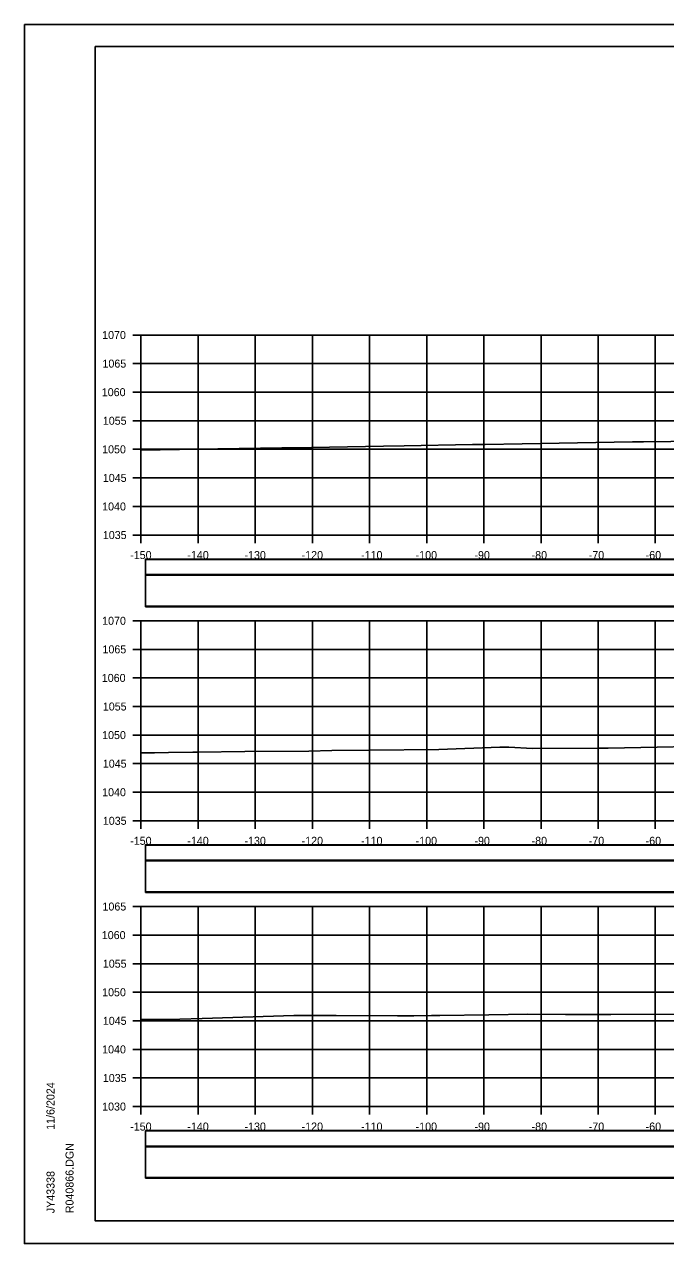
# Model space of a CAD drawing. Extents: x 1370565 to 1374448, y 301010 to 304637.
# Drawn here: x 1373198.4 to 1373310.6, y 303218.4 to 303431.7 of the extents above; entities that cross this region are included whole.
import ezdxf

# ---------------------------------------------------------------- set-up
doc = ezdxf.new("R2010")
doc.units = 0
for name, color, linetype in [('Default', 7, 'Continuous'), ('R_Axis', 7, 'Continuous'), ('R_Axis Annot', 7, 'Continuous'), ('R_Border', 7, 'Continuous'), ('R_Drive', 7, 'Continuous'), ('R_Exist Surface', 7, 'Continuous'), ('R_Grid', 7, 'Continuous'), ('R_No Plot', 7, 'Continuous')]:
    doc.layers.add(name, color=color, linetype=linetype)

msp = doc.modelspace()

# ---------------------------------------------------------------- linework, layer by layer
at = {"layer": 'Default'}
for points in [[(1373219.61, 303335.38), (1373518.02, 303335.38), (1373518.02, 303338.08), (1373219.61, 303338.08)], [(1373219.61, 303329.8), (1373518.02, 303329.8), (1373518.02, 303335.32), (1373219.61, 303335.32)], [(1373219.61, 303285.38), (1373518.02, 303285.38), (1373518.02, 303288.08), (1373219.61, 303288.08)], [(1373219.61, 303279.8), (1373518.02, 303279.8), (1373518.02, 303285.32), (1373219.61, 303285.32)], [(1373219.61, 303235.38), (1373518.02, 303235.38), (1373518.02, 303238.08), (1373219.61, 303238.08)], [(1373219.61, 303229.8), (1373518.02, 303229.8), (1373518.02, 303235.32), (1373219.61, 303235.32)]]:
    msp.add_lwpolyline(points, close=True, dxfattribs=at)
at = {"layer": 'R_Axis'}
for p, q in [((1373217.41, 303377.34), (1373218.81, 303377.34)), ((1373218.81, 303342.34), (1373218.81, 303377.34)), ((1373217.41, 303372.34), (1373218.81, 303372.34)), ((1373217.41, 303367.34), (1373218.81, 303367.34)), ((1373217.41, 303362.34), (1373218.81, 303362.34)), ((1373217.41, 303357.34), (1373218.81, 303357.34)), ((1373217.41, 303352.34), (1373218.81, 303352.34)), ((1373217.41, 303347.34), (1373218.81, 303347.34)), ((1373217.41, 303342.34), (1373218.81, 303342.34)), ((1373218.81, 303342.34), (1373518.81, 303342.34)), ((1373218.81, 303340.94), (1373218.81, 303342.34)), ((1373228.81, 303340.94), (1373228.81, 303342.34)), ((1373238.81, 303340.94), (1373238.81, 303342.34)), ((1373248.81, 303340.94), (1373248.81, 303342.34)), ((1373258.81, 303340.94), (1373258.81, 303342.34)), ((1373268.81, 303340.94), (1373268.81, 303342.34)), ((1373278.81, 303340.94), (1373278.81, 303342.34)), ((1373288.81, 303340.94), (1373288.81, 303342.34)), ((1373298.81, 303340.94), (1373298.81, 303342.34)), ((1373308.81, 303340.94), (1373308.81, 303342.34)), ((1373217.41, 303327.34), (1373218.81, 303327.34)), ((1373218.81, 303292.34), (1373218.81, 303327.34)), ((1373217.41, 303322.34), (1373218.81, 303322.34)), ((1373217.41, 303317.34), (1373218.81, 303317.34)), ((1373217.41, 303312.34), (1373218.81, 303312.34)), ((1373217.41, 303307.34), (1373218.81, 303307.34)), ((1373217.41, 303302.34), (1373218.81, 303302.34)), ((1373217.41, 303297.34), (1373218.81, 303297.34)), ((1373217.41, 303292.34), (1373218.81, 303292.34)), ((1373218.81, 303292.34), (1373518.81, 303292.34)), ((1373218.81, 303290.94), (1373218.81, 303292.34)), ((1373228.81, 303290.94), (1373228.81, 303292.34)), ((1373238.81, 303290.94), (1373238.81, 303292.34)), ((1373248.81, 303290.94), (1373248.81, 303292.34)), ((1373258.81, 303290.94), (1373258.81, 303292.34)), ((1373268.81, 303290.94), (1373268.81, 303292.34)), ((1373278.81, 303290.94), (1373278.81, 303292.34)), ((1373288.81, 303290.94), (1373288.81, 303292.34)), ((1373298.81, 303290.94), (1373298.81, 303292.34)), ((1373308.81, 303290.94), (1373308.81, 303292.34)), ((1373217.41, 303277.34), (1373218.81, 303277.34)), ((1373218.81, 303242.34), (1373218.81, 303277.34)), ((1373217.41, 303272.34), (1373218.81, 303272.34)), ((1373217.41, 303267.34), (1373218.81, 303267.34)), ((1373217.41, 303262.34), (1373218.81, 303262.34)), ((1373217.41, 303257.34), (1373218.81, 303257.34)), ((1373217.41, 303252.34), (1373218.81, 303252.34)), ((1373217.41, 303247.34), (1373218.81, 303247.34)), ((1373217.41, 303242.34), (1373218.81, 303242.34)), ((1373218.81, 303242.34), (1373518.81, 303242.34)), ((1373218.81, 303240.94), (1373218.81, 303242.34)), ((1373228.81, 303240.94), (1373228.81, 303242.34)), ((1373238.81, 303240.94), (1373238.81, 303242.34)), ((1373248.81, 303240.94), (1373248.81, 303242.34)), ((1373258.81, 303240.94), (1373258.81, 303242.34)), ((1373268.81, 303240.94), (1373268.81, 303242.34)), ((1373278.81, 303240.94), (1373278.81, 303242.34)), ((1373288.81, 303240.94), (1373288.81, 303242.34)), ((1373298.81, 303240.94), (1373298.81, 303242.34)), ((1373308.81, 303240.94), (1373308.81, 303242.34))]:
    msp.add_line(p, q, dxfattribs=at)
at = {"layer": 'R_Border'}
for p, q in [((1373210.81, 303427.8), (1373526.99, 303427.8)), ((1373210.81, 303222.34), (1373210.81, 303427.8)), ((1373210.81, 303222.34), (1373210.81, 303222.34)), ((1373526.99, 303222.34), (1373210.81, 303222.34))]:
    msp.add_line(p, q, dxfattribs=at)
at = {"layer": 'R_Drive'}
for points in [[(1373219.61, 303335.43), (1373518.02, 303335.43), (1373518.02, 303338.14), (1373219.61, 303338.14)], [(1373219.61, 303329.91), (1373518.02, 303329.91), (1373518.02, 303335.43), (1373219.61, 303335.43)], [(1373219.61, 303285.43), (1373518.02, 303285.43), (1373518.02, 303288.14), (1373219.61, 303288.14)], [(1373219.61, 303279.91), (1373518.02, 303279.91), (1373518.02, 303285.43), (1373219.61, 303285.43)], [(1373219.61, 303235.43), (1373518.02, 303235.43), (1373518.02, 303238.14), (1373219.61, 303238.14)], [(1373219.61, 303229.91), (1373518.02, 303229.91), (1373518.02, 303235.43), (1373219.61, 303235.43)]]:
    msp.add_lwpolyline(points, close=True, dxfattribs=at)
at = {"layer": 'R_Exist Surface'}
for points in [[(1373218.81, 303357.17), (1373225.54, 303357.29), (1373232.27, 303357.4), (1373243.47, 303357.59), (1373248.62, 303357.68), (1373261.25, 303357.9), (1373264.87, 303357.96), (1373276.84, 303358.16), (1373279.05, 303358.19), (1373291.96, 303358.42), (1373304.8, 303358.64), (1373306.62, 303358.66), (1373306.77, 303358.66), (1373321.12, 303358.85)], [(1373218.81, 303304.23), (1373221.2, 303304.26), (1373223.61, 303304.28), (1373227.88, 303304.35), (1373228.76, 303304.37), (1373236.98, 303304.45), (1373248.16, 303304.55), (1373252.19, 303304.63), (1373258.71, 303304.69), (1373270.92, 303304.8), (1373281.61, 303305.23), (1373283.17, 303305.23), (1373287.3, 303304.97), (1373298.95, 303305.07), (1373300.17, 303305.07), (1373300.56, 303305.06), (1373323.35, 303305.53)], [(1373218.81, 303257.57), (1373222.11, 303257.57), (1373223.48, 303257.59), (1373225.62, 303257.65), (1373229.53, 303257.74), (1373245.53, 303258.3), (1373252.98, 303258.28), (1373263.7, 303258.23), (1373266.58, 303258.23), (1373269.67, 303258.3), (1373271.1, 303258.29), (1373279.69, 303258.41), (1373286.49, 303258.52), (1373293.12, 303258.43), (1373301.02, 303258.44), (1373320.91, 303258.53)]]:
    msp.add_lwpolyline(points, dxfattribs=at)
at = {"layer": 'R_Grid'}
for p, q in [((1373218.81, 303377.34), (1373518.81, 303377.34)), ((1373218.81, 303342.34), (1373218.81, 303377.34)), ((1373228.81, 303342.34), (1373228.81, 303377.34)), ((1373238.81, 303342.34), (1373238.81, 303377.34)), ((1373248.81, 303342.34), (1373248.81, 303377.34)), ((1373258.81, 303342.34), (1373258.81, 303377.34)), ((1373268.81, 303342.34), (1373268.81, 303377.34)), ((1373278.81, 303342.34), (1373278.81, 303377.34)), ((1373288.81, 303342.34), (1373288.81, 303377.34)), ((1373298.81, 303342.34), (1373298.81, 303377.34)), ((1373308.81, 303342.34), (1373308.81, 303377.34)), ((1373218.81, 303372.34), (1373518.81, 303372.34)), ((1373218.81, 303367.34), (1373518.81, 303367.34)), ((1373218.81, 303362.34), (1373518.81, 303362.34)), ((1373218.81, 303357.34), (1373518.81, 303357.34)), ((1373218.81, 303352.34), (1373518.81, 303352.34)), ((1373218.81, 303347.34), (1373518.81, 303347.34)), ((1373218.81, 303342.34), (1373518.81, 303342.34)), ((1373218.81, 303327.34), (1373518.81, 303327.34)), ((1373218.81, 303292.34), (1373218.81, 303327.34)), ((1373228.81, 303292.34), (1373228.81, 303327.34)), ((1373238.81, 303292.34), (1373238.81, 303327.34)), ((1373248.81, 303292.34), (1373248.81, 303327.34)), ((1373258.81, 303292.34), (1373258.81, 303327.34)), ((1373268.81, 303292.34), (1373268.81, 303327.34)), ((1373278.81, 303292.34), (1373278.81, 303327.34)), ((1373288.81, 303292.34), (1373288.81, 303327.34)), ((1373298.81, 303292.34), (1373298.81, 303327.34)), ((1373308.81, 303292.34), (1373308.81, 303327.34)), ((1373218.81, 303322.34), (1373518.81, 303322.34)), ((1373218.81, 303317.34), (1373518.81, 303317.34)), ((1373218.81, 303312.34), (1373518.81, 303312.34)), ((1373218.81, 303307.34), (1373518.81, 303307.34)), ((1373218.81, 303302.34), (1373518.81, 303302.34)), ((1373218.81, 303297.34), (1373518.81, 303297.34)), ((1373218.81, 303292.34), (1373518.81, 303292.34)), ((1373218.81, 303277.34), (1373518.81, 303277.34)), ((1373218.81, 303242.34), (1373218.81, 303277.34)), ((1373228.81, 303242.34), (1373228.81, 303277.34)), ((1373238.81, 303242.34), (1373238.81, 303277.34)), ((1373248.81, 303242.34), (1373248.81, 303277.34)), ((1373258.81, 303242.34), (1373258.81, 303277.34)), ((1373268.81, 303242.34), (1373268.81, 303277.34)), ((1373278.81, 303242.34), (1373278.81, 303277.34)), ((1373288.81, 303242.34), (1373288.81, 303277.34)), ((1373298.81, 303242.34), (1373298.81, 303277.34)), ((1373308.81, 303242.34), (1373308.81, 303277.34)), ((1373218.81, 303272.34), (1373518.81, 303272.34)), ((1373218.81, 303267.34), (1373518.81, 303267.34)), ((1373218.81, 303262.34), (1373518.81, 303262.34)), ((1373218.81, 303257.34), (1373518.81, 303257.34)), ((1373218.81, 303252.34), (1373518.81, 303252.34)), ((1373218.81, 303247.34), (1373518.81, 303247.34)), ((1373218.81, 303242.34), (1373518.81, 303242.34))]:
    msp.add_line(p, q, dxfattribs=at)
at = {"layer": 'R_No Plot'}
for p, q in [((1373198.41, 303431.69), (1373531.75, 303431.69)), ((1373198.41, 303218.36), (1373531.75, 303218.36))]:
    msp.add_line(p, q, dxfattribs=at)
for points in [[(1373198.41, 303431.69), (1373531.75, 303431.69), (1373531.75, 303218.36), (1373198.41, 303218.36)], [(1373444.73, 303427.8), (1373464.35, 303427.8), (1373464.35, 303417.92), (1373480.47, 303417.92), (1373503.67, 303417.92), (1373503.67, 303393.59), (1373526.99, 303393.59), (1373526.99, 303222.34), (1373210.81, 303222.34), (1373210.81, 303427.8)]]:
    msp.add_lwpolyline(points, close=True, dxfattribs=at)

# ---------------------------------------------------------------- texts
at = {"layer": 'R_Axis Annot'}
for s, p in [('1070', (1373212.01, 303376.64)), ('1065', (1373212.07, 303371.64)), ('1060', (1373211.95, 303366.64)), ('1055', (1373212.13, 303361.64)), ('1050', (1373212.01, 303356.64)), ('1045', (1373212.13, 303351.64)), ('1040', (1373212.01, 303346.64)), ('1035', (1373212.13, 303341.64)), ('-150', (1373216.92, 303338.14)), ('-140', (1373226.92, 303338.14)), ('-130', (1373236.92, 303338.14)), ('-120', (1373246.92, 303338.14)), ('-110', (1373257.32, 303338.14)), ('-100', (1373266.87, 303338.14)), ('-90', (1373277.16, 303338.14)), ('-80', (1373287.16, 303338.14)), ('-70', (1373297.16, 303338.14)), ('-60', (1373307.12, 303338.14)), ('1070', (1373212.01, 303326.64)), ('1065', (1373212.07, 303321.64)), ('1060', (1373211.95, 303316.64)), ('1055', (1373212.13, 303311.64)), ('1050', (1373212.01, 303306.64)), ('1045', (1373212.13, 303301.64)), ('1040', (1373212.01, 303296.64)), ('1035', (1373212.13, 303291.64)), ('-150', (1373216.92, 303288.14)), ('-140', (1373226.92, 303288.14)), ('-130', (1373236.92, 303288.14)), ('-120', (1373246.92, 303288.14)), ('-110', (1373257.32, 303288.14)), ('-100', (1373266.87, 303288.14)), ('-90', (1373277.16, 303288.14)), ('-80', (1373287.16, 303288.14)), ('-70', (1373297.16, 303288.14)), ('-60', (1373307.12, 303288.14)), ('1065', (1373212.07, 303276.64)), ('1060', (1373211.95, 303271.64)), ('1055', (1373212.13, 303266.64)), ('1050', (1373212.01, 303261.64)), ('1045', (1373212.13, 303256.64)), ('1040', (1373212.01, 303251.64)), ('1035', (1373212.13, 303246.64)), ('1030', (1373212.01, 303241.64)), ('-150', (1373216.92, 303238.14)), ('-140', (1373226.92, 303238.14)), ('-130', (1373236.92, 303238.14)), ('-120', (1373246.92, 303238.14)), ('-110', (1373257.32, 303238.14)), ('-100', (1373266.87, 303238.14)), ('-90', (1373277.16, 303238.14)), ('-80', (1373287.16, 303238.14)), ('-70', (1373297.16, 303238.14)), ('-60', (1373307.12, 303238.14))]:
    msp.add_text(s, height=1.4, dxfattribs=at).set_placement(p)
at = {"layer": 'R_Border'}
for s, p in [('11/6/2024', (1373203.68, 303238.27)), ('R040866.DGN', (1373207.01, 303223.67)), ('JY43338', (1373203.68, 303223.67))]:
    msp.add_text(s, height=1.4, rotation=90, dxfattribs=at).set_placement(p)

doc.saveas('drawing.dxf')
